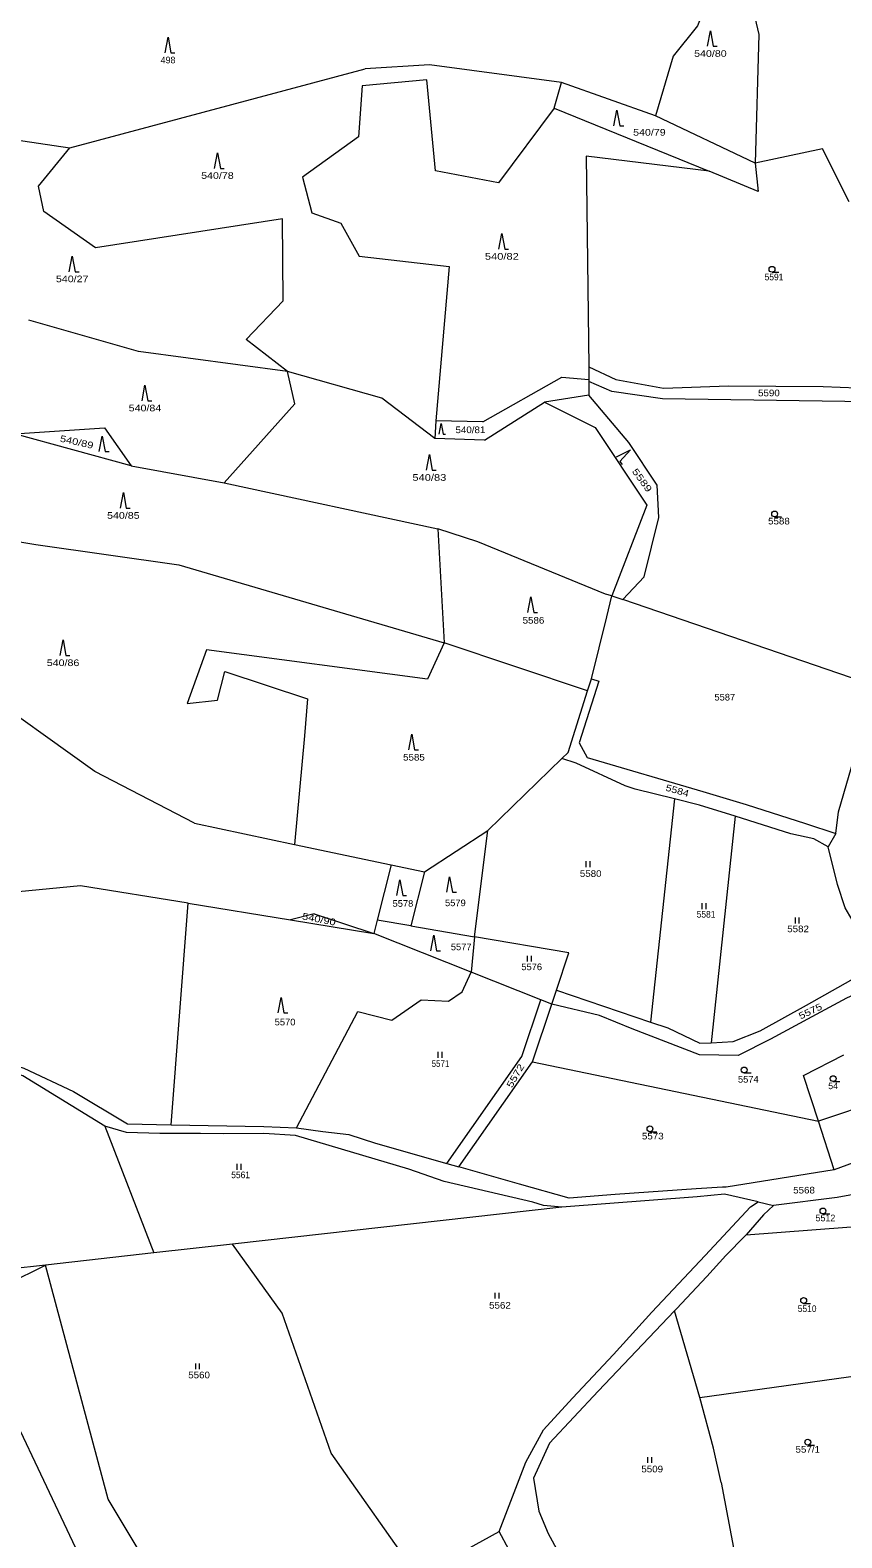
# Model space of a CAD drawing. Extents: x -590528 to -586543, y -1119609 to -1116685.
# Drawn here: x -589555 to -589346.9, y -1118589.8 to -1118203.4 of the extents above; entities that cross this region are included whole.
import ezdxf
from ezdxf.enums import TextEntityAlignment as Align

# ---------------------------------------------------------------- set-up
doc = ezdxf.new("R2010")
doc.units = 0
doc.header["$LTSCALE"] = 0.68
for name, color, linetype, lineweight in [('1', 7, 'Continuous', 13), ('3', 7, 'Continuous', 13), ('6', 7, 'Continuous', 13)]:
    doc.layers.add(name, color=color, linetype=linetype, lineweight=lineweight)

msp = doc.modelspace()

# ---------------------------------------------------------------- linework, layer by layer
at = {"layer": '1'}
for p, q in [((-589420.7, -1118223.43), (-589418.81, -1118216.86)), ((-589420.7, -1118223.43), (-589434.91, -1118242.53)), ((-589420.7, -1118223.43), (-589380.95, -1118239.53)), ((-589369.19, -1118237.51), (-589394.68, -1118225.42)), ((-589380.95, -1118239.53), (-589412.44, -1118235.73)), ((-589412.44, -1118235.73), (-589411.8, -1118289.7)), ((-589351.94, -1118233.83), (-589369.19, -1118237.51)), ((-589345.1, -1118247.45), (-589351.94, -1118233.83)), ((-589434.91, -1118242.53), (-589451.09, -1118239.45)), ((-589368.37, -1118244.74), (-589380.95, -1118239.53)), ((-589369.19, -1118237.51), (-589368.37, -1118244.74)), ((-589411.8, -1118289.7), (-589411.76, -1118292.96)), ((-589438.94, -1118303.82), (-589418.67, -1118292.32)), ((-589418.67, -1118292.32), (-589411.76, -1118292.96)), ((-589411.77, -1118296.96), (-589423.17, -1118298.79)), ((-589438.53, -1118308.5), (-589423.17, -1118298.79)), ((-589423.17, -1118298.79), (-589410.2, -1118305.29)), ((-589438.94, -1118303.82), (-589450.98, -1118303.51)), ((-589410.2, -1118305.29), (-589396.96, -1118325.15)), ((-589438.53, -1118308.5), (-589451.27, -1118308.04)), ((-589529.09, -1118315.11), (-589505.23, -1118319.44)), ((-589505.23, -1118319.44), (-589450.51, -1118331.19)), ((-589440.23, -1118334.53), (-589450.51, -1118331.19)), ((-589450.51, -1118331.19), (-589448.85, -1118360.45)), ((-589553.49, -1118335.27), (-589516.89, -1118340.44)), ((-589407.55, -1118347.96), (-589440.23, -1118334.53)), ((-589516.89, -1118340.44), (-589448.85, -1118360.45)), ((-589405.9, -1118348.38), (-589403.04, -1118349.36)), ((-589338.39, -1118371.5), (-589403.04, -1118349.36)), ((-589509.74, -1118362.23), (-589514.73, -1118375.97)), ((-589453.1, -1118369.77), (-589509.74, -1118362.23)), ((-589448.85, -1118360.45), (-589453.1, -1118369.77)), ((-589412.11, -1118372.75), (-589448.85, -1118360.45)), ((-589506.92, -1118375.12), (-589505.08, -1118367.82)), ((-589514.73, -1118375.97), (-589506.92, -1118375.12)), ((-589374.32, -1118404.86), (-589383.45, -1118402.03)), ((-589512.85, -1118406.67), (-589487.24, -1118412.16)), ((-589441.07, -1118435.78), (-589437.66, -1118408.57)), ((-589348.52, -1118409.33), (-589350.46, -1118412.71)), ((-589487.24, -1118412.16), (-589462.45, -1118417.32)), ((-589462.45, -1118417.32), (-589466.02, -1118431.51)), ((-589542.02, -1118422.69), (-589626.1, -1118430.96)), ((-589514.46, -1118427.18), (-589542.02, -1118422.69)), ((-589482.16, -1118429.93), (-589488.26, -1118431.44)), ((-589482.16, -1118429.93), (-589466.88, -1118434.92)), ((-589466.02, -1118431.51), (-589466.88, -1118434.92)), ((-589457.41, -1118432.98), (-589466.02, -1118431.51)), ((-589441.91, -1118444.85), (-589466.88, -1118434.92)), ((-589424.08, -1118451.93), (-589441.91, -1118444.85)), ((-589420.1, -1118449.48), (-589395.94, -1118457.67)), ((-589383.3, -1118463.06), (-589380.45, -1118462.92)), ((-589356.8, -1118471.32), (-589346.46, -1118466.02)), ((-589426.23, -1118467.83), (-589352.94, -1118483.06)), ((-589352.94, -1118483.06), (-589356.8, -1118471.32)), ((-589348.93, -1118495.49), (-589352.94, -1118483.06)), ((-589518.8, -1118483.93), (-589495.1, -1118484.36)), ((-589331.9, -1118489.22), (-589348.93, -1118495.49)), ((-589377.05, -1118501.76), (-589384.03, -1118502.43)), ((-589368.38, -1118503.73), (-589364.48, -1118504.62)), ((-589371.72, -1118512.45), (-589371.5, -1118512.2)), ((-589534.97, -1118579.92), (-589551.05, -1118519.91)), ((-589383.31, -1118553.86), (-589336.43, -1118547.3)), ((-589379.87, -1118566.79), (-589383.31, -1118553.86)), ((-589377.91, -1118575.64), (-589379.87, -1118566.79)), ((-589377.91, -1118575.64), (-589372.7, -1118602.82)), ((-589498.15, -1118641.31), (-589534.97, -1118579.92)), ((-589429.8, -1118597.4), (-589434.75, -1118588.2))]:
    msp.add_line(p, q, dxfattribs=at)
for points in [[(-589372.48, -1118152.76), (-589373, -1118163.51), (-589373.75, -1118180.26), (-589377.73, -1118179.44), (-589379.13, -1118188.24), (-589371.82, -1118189.25), (-589368.25, -1118204.56), (-589369.19, -1118237.51)], [(-589382.5, -1118198.72), (-589383.94, -1118202.31), (-589390.13, -1118210.09), (-589394.68, -1118225.42), (-589418.81, -1118216.86), (-589452.58, -1118212.28), (-589469.1, -1118213.35)], [(-589606.63, -1118216.6), (-589577.04, -1118228.83), (-589544.83, -1118233.58), (-589469.1, -1118213.35)], [(-589451.09, -1118239.45), (-589453.33, -1118216.17), (-589469.89, -1118217.69), (-589470.84, -1118230.74), (-589485.16, -1118241.1)], [(-589490.32, -1118251.82), (-589538.21, -1118259.2), (-589551.46, -1118249.92), (-589552.85, -1118243.43), (-589544.83, -1118233.58)], [(-589485.16, -1118241.1), (-589482.8, -1118250.27), (-589475.37, -1118252.87), (-589470.68, -1118261.39), (-589447.54, -1118263.97), (-589450.98, -1118303.51), (-589451.27, -1118308.04), (-589464.84, -1118297.73), (-589488.97, -1118290.89), (-589499.57, -1118282.67), (-589490.11, -1118272.83), (-589490.32, -1118251.82)], [(-589375.98, -1118294.62), (-589351.74, -1118294.77), (-589338.64, -1118295.23), (-589329.98, -1118296.79), (-589329.91, -1118292.36), (-589329.64, -1118274.9), (-589329.45, -1118254.79)], [(-589488.97, -1118290.89), (-589527.21, -1118285.75), (-589555.33, -1118277.78)], [(-589411.8, -1118289.7), (-589404.83, -1118292.98), (-589392.63, -1118295.18), (-589375.98, -1118294.62)], [(-589505.23, -1118319.44), (-589487.11, -1118299.2), (-589488.97, -1118290.89)], [(-589411.76, -1118292.96), (-589411.76, -1118293.48), (-589411.77, -1118296.96)], [(-589392.94, -1118297.95), (-589405.89, -1118296.01), (-589411.76, -1118293.48)], [(-589393.86, -1118328.35), (-589394.29, -1118320.07), (-589401.51, -1118309.07), (-589411.77, -1118296.96)], [(-589330.68, -1118329.38), (-589330.39, -1118306.1), (-589329.42, -1118301.15), (-589334.45, -1118298.8), (-589392.94, -1118297.95)], [(-589396.96, -1118325.15), (-589405.9, -1118348.38), (-589407.55, -1118347.96)], [(-589403.04, -1118349.36), (-589397.63, -1118343.52), (-589393.86, -1118328.35)], [(-589596.66, -1118331.88), (-589578.03, -1118331.14), (-589553.49, -1118335.27)], [(-589462.45, -1118417.32), (-589453.92, -1118419.14), (-589437.66, -1118408.57), (-589418.7, -1118390.11), (-589417.11, -1118388.58), (-589412.11, -1118372.75), (-589411.14, -1118369.69), (-589407.15, -1118353.8), (-589405.9, -1118348.38)], [(-589512.85, -1118406.67), (-589538.43, -1118393.38), (-589569.51, -1118371.22), (-589606.9, -1118355.31)], [(-589505.08, -1118367.82), (-589483.92, -1118374.79), (-589484.68, -1118384.29), (-589487.24, -1118412.16)], [(-589411.14, -1118369.69), (-589409.23, -1118370.29), (-589414.23, -1118386.1), (-589412.25, -1118389.81), (-589382.59, -1118398.58)], [(-589382.59, -1118398.58), (-589371.5, -1118401.89), (-589356.23, -1118406.75), (-589348.52, -1118409.33), (-589347.77, -1118403.74), (-589338.39, -1118371.5)], [(-589383.45, -1118402.03), (-589389.8, -1118400.43), (-589399.89, -1118397.91), (-589402.48, -1118397.1), (-589415.06, -1118391.26), (-589418.7, -1118390.11)], [(-589389.8, -1118400.43), (-589395.94, -1118457.67), (-589391.57, -1118459.15), (-589383.3, -1118463.06)], [(-589374.32, -1118404.86), (-589380.45, -1118462.92), (-589374.76, -1118462.64), (-589367.9, -1118459.92), (-589356.04, -1118453.27), (-589344.63, -1118446.86), (-589337.38, -1118442.01), (-589341.33, -1118436.52), (-589346.1, -1118428.33), (-589348.05, -1118422.4)], [(-589348.05, -1118422.4), (-589350.46, -1118412.71), (-589354.1, -1118410.65), (-589360.05, -1118409.36), (-589374.32, -1118404.86)], [(-589453.92, -1118419.14), (-589457.41, -1118432.98), (-589441.07, -1118435.78), (-589441.91, -1118444.85)], [(-589626.1, -1118430.96), (-589627.36, -1118434.04), (-589623.95, -1118439.1), (-589617.85, -1118446.45), (-589612.06, -1118450.99), (-589605.04, -1118454.87), (-589571.63, -1118464.71), (-589556.61, -1118469.42), (-589543.84, -1118475.46), (-589529.99, -1118483.72), (-589518.8, -1118483.93), (-589514.46, -1118427.18)], [(-589514.46, -1118427.18), (-589488.26, -1118431.44), (-589466.88, -1118434.92)], [(-589421.29, -1118453.04), (-589420.1, -1118449.48), (-589416.91, -1118439.92), (-589441.07, -1118435.78)], [(-589495.1, -1118484.36), (-589486.71, -1118484.73), (-589470.96, -1118454.91), (-589462.26, -1118457.18), (-589454.77, -1118451.97), (-589447.77, -1118452.27), (-589444.28, -1118449.87), (-589441.91, -1118444.85)], [(-589331.37, -1118445.01), (-589345.78, -1118451.54), (-589354.64, -1118456.32), (-589365.2, -1118462.01), (-589373.54, -1118466.17), (-589383.43, -1118465.99)], [(-589486.71, -1118484.73), (-589479.92, -1118485.7), (-589473.28, -1118486.43), (-589466.42, -1118488.65), (-589448.18, -1118493.85), (-589428.94, -1118466.46), (-589424.08, -1118451.93)], [(-589448.18, -1118493.85), (-589445.13, -1118494.72), (-589426.23, -1118467.83), (-589421.29, -1118453.04), (-589424.08, -1118451.93)], [(-589383.43, -1118465.99), (-589400.66, -1118459.35), (-589409.05, -1118455.96), (-589421.29, -1118453.04)], [(-589535.79, -1118484.33), (-589556.88, -1118471.45), (-589572.23, -1118466.61), (-589589.8, -1118461.61)], [(-589335.16, -1118476.28), (-589337.12, -1118477.71), (-589352.94, -1118483.06)], [(-589505.36, -1118486.26), (-589511.31, -1118486.21), (-589521.73, -1118486.16), (-589530.26, -1118485.9), (-589535.79, -1118484.33), (-589523.26, -1118516.81)], [(-589418.68, -1118505.11), (-589423.38, -1118504.67), (-589426.14, -1118503.75), (-589448.86, -1118498.46), (-589457.93, -1118495.32), (-589486.98, -1118486.69), (-589495.07, -1118486.19), (-589505.36, -1118486.26)], [(-589384.3, -1118500.39), (-589405.04, -1118501.78), (-589416.8, -1118502.8), (-589429.55, -1118499.16), (-589445.13, -1118494.72)], [(-589348.93, -1118495.49), (-589376.6, -1118499.92), (-589377.5, -1118499.93), (-589384.3, -1118500.39)], [(-589384.03, -1118502.43), (-589418.68, -1118505.11), (-589503.08, -1118514.55)], [(-589381.98, -1118517.45), (-589370.36, -1118505.02), (-589368.38, -1118503.73), (-589377.05, -1118501.76)], [(-589381.53, -1118522.85), (-589376.68, -1118517.42), (-589371.72, -1118512.45)], [(-589503.08, -1118514.55), (-589523.26, -1118516.81), (-589551.05, -1118519.91)], [(-589455.19, -1118600.2), (-589477.85, -1118568.1), (-589490.34, -1118532.23), (-589503.08, -1118514.55)], [(-589455.19, -1118600.2), (-589453.19, -1118598.32), (-589434.75, -1118588.2), (-589427.97, -1118570.44), (-589423.37, -1118562.13), (-589416.01, -1118553.98), (-589405.46, -1118542.79), (-589395.65, -1118531.99), (-589381.98, -1118517.45)], [(-589536.6, -1118606.53), (-589558.87, -1118559.4), (-589570.68, -1118533.18), (-589560.7, -1118524.73), (-589551.05, -1118519.91), (-589569.71, -1118522), (-589581.21, -1118530.01)], [(-589389.82, -1118531.63), (-589389.33, -1118531.12), (-589381.53, -1118522.85)], [(-589383.31, -1118553.86), (-589389.82, -1118531.63), (-589409.4, -1118552.26), (-589421.86, -1118565.56), (-589425.96, -1118574.55), (-589424.61, -1118582.96), (-589422.21, -1118588.7), (-589411.59, -1118608.16)]]:
    msp.add_lwpolyline(points, dxfattribs=at)
for points in [[(-589558.94, -1118306.87), (-589535.95, -1118305.36), (-589529.09, -1118315.11)], [(-589336.66, -1118509.48), (-589338.42, -1118500.8), (-589348.14, -1118502.62), (-589364.48, -1118504.62), (-589366.99, -1118507.07), (-589371.5, -1118512.2)]]:
    msp.add_lwpolyline(points, close=True, dxfattribs=at)
at = {"layer": '6'}
for p, q in [((-589364.84, -1118265.46), (-589363.09, -1118265.46)), ((-589364.17, -1118328.16), (-589362.42, -1118328.16)), ((-589412.43, -1118417.91), (-589412.43, -1118416.41)), ((-589411.43, -1118417.91), (-589411.43, -1118416.41)), ((-589382.75, -1118428.68), (-589382.75, -1118427.18)), ((-589381.75, -1118428.68), (-589381.75, -1118427.18)), ((-589358.85, -1118432.34), (-589358.85, -1118430.84)), ((-589357.85, -1118432.34), (-589357.85, -1118430.84)), ((-589427.47, -1118442.12), (-589427.47, -1118440.62)), ((-589426.47, -1118442.12), (-589426.47, -1118440.62)), ((-589450.41, -1118466.79), (-589450.41, -1118465.29)), ((-589449.41, -1118466.79), (-589449.41, -1118465.29)), ((-589371.97, -1118470.66), (-589370.22, -1118470.66)), ((-589349.17, -1118472.87), (-589347.42, -1118472.87)), ((-589396.12, -1118485.74), (-589394.37, -1118485.74)), ((-589501.91, -1118495.49), (-589501.91, -1118493.99)), ((-589500.91, -1118495.49), (-589500.91, -1118493.99)), ((-589351.78, -1118506.79), (-589350.03, -1118506.79)), ((-589435.77, -1118528.5), (-589435.77, -1118527)), ((-589434.77, -1118528.5), (-589434.77, -1118527)), ((-589356.73, -1118529.76), (-589354.98, -1118529.76)), ((-589512.53, -1118546.61), (-589512.53, -1118545.11)), ((-589511.53, -1118546.61), (-589511.53, -1118545.11)), ((-589355.68, -1118566.04), (-589353.93, -1118566.04)), ((-589396.64, -1118570.63), (-589396.64, -1118569.13)), ((-589395.64, -1118570.63), (-589395.64, -1118569.13))]:
    msp.add_line(p, q, dxfattribs=at)
for points in [[(-589381.38, -1118207.56), (-589380.63, -1118203.56), (-589379.88, -1118207.56), (-589378.88, -1118207.56)], [(-589520.38, -1118209.23), (-589519.63, -1118205.23), (-589518.88, -1118209.23), (-589517.88, -1118209.23)], [(-589405.35, -1118227.93), (-589404.6, -1118223.93), (-589403.85, -1118227.93), (-589402.85, -1118227.93)], [(-589507.72, -1118238.84), (-589506.97, -1118234.84), (-589506.22, -1118238.84), (-589505.22, -1118238.84)], [(-589434.83, -1118259.56), (-589434.08, -1118255.56), (-589433.33, -1118259.56), (-589432.33, -1118259.56)], [(-589544.94, -1118265.32), (-589544.19, -1118261.32), (-589543.44, -1118265.32), (-589542.44, -1118265.32)], [(-589526.29, -1118298.42), (-589525.54, -1118294.42), (-589524.79, -1118298.42), (-589523.79, -1118298.42)], [(-589450.162, -1118306.94), (-589449.66, -1118304.26), (-589449.158, -1118306.94), (-589448.488, -1118306.94)], [(-589537.24, -1118311.44), (-589536.49, -1118307.44), (-589535.74, -1118311.44), (-589534.74, -1118311.44)], [(-589453.4, -1118316.21), (-589452.65, -1118312.21), (-589451.9, -1118316.21), (-589450.9, -1118316.21)], [(-589404.729, -1118312.75), (-589401.078, -1118310.953), (-589403.831, -1118313.95), (-589403.231, -1118314.751)], [(-589531.83, -1118325.95), (-589531.08, -1118321.95), (-589530.33, -1118325.95), (-589529.33, -1118325.95)], [(-589427.42, -1118352.66), (-589426.67, -1118348.66), (-589425.92, -1118352.66), (-589424.92, -1118352.66)], [(-589547.28, -1118363.7), (-589546.53, -1118359.7), (-589545.78, -1118363.7), (-589544.78, -1118363.7)], [(-589457.92, -1118387.83), (-589457.17, -1118383.83), (-589456.42, -1118387.83), (-589455.42, -1118387.83)], [(-589460.98, -1118425.19), (-589460.23, -1118421.19), (-589459.48, -1118425.19), (-589458.48, -1118425.19)], [(-589448.21, -1118424.38), (-589447.46, -1118420.38), (-589446.71, -1118424.38), (-589445.71, -1118424.38)], [(-589452.3, -1118439.35), (-589451.55, -1118435.35), (-589450.8, -1118439.35), (-589449.8, -1118439.35)], [(-589491.41, -1118455.3), (-589490.66, -1118451.3), (-589489.91, -1118455.3), (-589488.91, -1118455.3)]]:
    msp.add_lwpolyline(points, dxfattribs=at)
for centre in [(-589364.84, -1118264.71), (-589364.17, -1118327.41), (-589371.97, -1118469.91), (-589349.17, -1118472.12), (-589396.12, -1118484.99), (-589351.78, -1118506.04), (-589356.73, -1118529.01), (-589355.68, -1118565.29)]:
    msp.add_circle(centre, 0.75, dxfattribs=at)

# ---------------------------------------------------------------- texts
at = {"layer": '3'}
for s, width, p in [('540/80', 1.2, (-589380.6305, -1118210.26)), ('540/79', 1.2, (-589396.2605, -1118230.46)), ('540/78', 1.2, (-589506.97, -1118241.54)), ('540/82', 1.25, (-589434.08, -1118262.26)), ('540/27', 1.2, (-589544.1905, -1118268.02)), ('540/84', 1.2, (-589525.5405, -1118301.12)), ('540/81', 1.1, (-589442.1305, -1118306.7)), ('540/83', 1.25, (-589452.6505, -1118318.91)), ('540/85', 1.2, (-589531.0805, -1118328.65)), ('540/86', 1.2, (-589546.5305, -1118366.4)), ('557/1', 1.1, (-589355.6805, -1118567.99))]:
    msp.add_text(s, height=1.7, dxfattribs=dict(at, width=width)).set_placement(p, align=Align.CENTER)
for s, p in [('498', (-589519.63, -1118211.93)), ('54', (-589349.1705, -1118474.82))]:
    msp.add_text(s, height=1.7, dxfattribs=at).set_placement(p, align=Align.CENTER)
for s, width, p in [('5591', 0.95, (-589366.733, -1118267.53)), ('5590', 1.1, (-589368.413, -1118297.25)), ('5588', 1.1, (-589365.843, -1118330.1)), ('5586', 1.1, (-589428.753, -1118355.52)), ('5587', 1.05, (-589379.593, -1118375.22)), ('5585', 1.1, (-589459.383, -1118390.62)), ('5580', 1.1, (-589414.093, -1118420.42)), ('5578', 1.05, (-589462.083, -1118428.09)), ('5579', 1.05, (-589448.643, -1118427.93)), ('5581', 0.95, (-589384.143, -1118430.86)), ('5582', 1.1, (-589360.943, -1118434.6)), ('5577', 1.05, (-589447.153, -1118439.22)), ('5576', 1.05, (-589429.083, -1118444.33)), ('5570', 1.05, (-589492.293, -1118458.48)), ('5571', 0.9, (-589452.083, -1118469.12)), ('5574', 1.05, (-589373.563, -1118473.15)), ('5573', 1.1, (-589398.173, -1118487.71)), ('5561', 0.95, (-589503.433, -1118497.64)), ('5568', 1.1, (-589359.413, -1118501.56)), ('5562', 1.1, (-589437.343, -1118531.07)), ('5510', 0.95, (-589358.233, -1118531.93)), ('5560', 1.1, (-589514.453, -1118548.93)), ('5509', 1.1, (-589398.323, -1118573.03))]:
    msp.add_text(s, height=1.7, dxfattribs=dict(at, width=width)).set_placement(p)
at = {"layer": '3', "width": 1.25}
for s, rotation, p in [('540/89', 347.556, (-589543.2072, -1118309.7804)), ('540/90', 349.16, (-589481.0988, -1118432.1107))]:
    msp.add_text(s, height=1.7, rotation=rotation, dxfattribs=at).set_placement(p, align=Align.CENTER)
at = {"layer": '3'}
for s, rotation, width, p in [('5589', 305.959, 1.35, (-589400.831, -1118316.502)), ('5584', 344.176, 1.2, (-589392.252, -1118398.295)), ('5575', 25.497, 1.25, (-589357.496, -1118456.988)), ('5572', 59.874, 1.3, (-589431.521, -1118474.665))]:
    msp.add_text(s, height=1.7, rotation=rotation, dxfattribs=dict(at, width=width)).set_placement(p)
msp.add_text('5512', height=1.7, dxfattribs=at).set_placement((-589353.673, -1118508.68))

doc.saveas('drawing.dxf')
